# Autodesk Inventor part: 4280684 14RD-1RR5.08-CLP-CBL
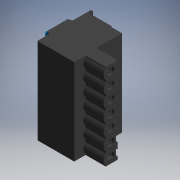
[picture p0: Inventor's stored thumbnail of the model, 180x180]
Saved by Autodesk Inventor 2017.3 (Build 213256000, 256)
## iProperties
Part Number: 4280684 14RD-1RR5.08-CLP-CBL
Material: Generic
Catalog Web Link: www.cadenas.de
Description: NEKM-C6 (p)-Terminal strip
Vendor: FESTO
Document SubType Name: Modeling
Designer: partserver
Manufacturer: FESTO
Mass: 12.0121 g
Surface Area: 60.2183 cm^2
Volume: 12.0121 cm^3
Density: 1 g/cm^3
Appearance: PSOLRGB-80-80-80
Category: PARTsolutions
Company: FESTO
Title: 4280684 14RD-1RR5.08-CLP-CBL
Author: Cadenas PARTsolutions
Comments: Terminal strip
PSOL_IDENT_0: {$CADENAS_DATA\23d-libs\festo\parts\n\nekm\parts\nekm_c6_parts.prj},201 {VTYP=3D},{NB=4280684 14RD-1
PSOL_IDENT_1: RR5.08-CLP-CBL},{LINA=4280684 14RD-1RR5.08-CLP-CBL},{NN=NEKM-C6 (p)},{DATE=16.05.2019 05:36:58},{GEO
PSOL_IDENT_2: MDATE=16.05.2019 05:36:56},{VERSION=},{LINEID=70},{WBVAR=},{WBNUMERIC=}  {NB=4280684 14RD-1RR5.08-CL
PSOL_IDENT_3: P-CBL},{LINA=4280684 14RD-1RR5.08-CLP-CBL},{KT=DUMMY},{TNR=4280684},{TYP=14RD-1RR5.08-CLP-CBL},{VERS=
PSOL_IDENT_4: 4},{N=7},{L=35.460},{L1=0.000}
NB: 4280684 14RD-1RR5.08-CLP-CBL
NN: NEKM-C6 (p)
NT: Terminal strip
NBSYN: $TNR. $TYP.
LINA: 4280684 14RD-1RR5.08-CLP-CBL
CATALOG: Festo
TNR: 4280684
TYP: 14RD-1RR5.08-CLP-CBL
VERS: 4
N: 7
L: 35.46
L1: 0
SUPPLIER: FESTO
ARTICLENO: 4280684 14RD-1RR5.08-CLP-CBL
BOMINFO: 4280684 14RD-1RR5.08-CLP-CBL
CREATOR: CADENAS GmbH
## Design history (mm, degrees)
sketch "Sketch_1"
  geometry: L1 (-0.5, -11.05)-(14.5, -11.05); L2 (14.7, -10.85)-(14.7, -6.415); L3 (14.897, -6.133)-(16.003, -5.731); L4 (16.2, -5.449)-(16.2, 2.789); L5 (16.003, 3.071)-(14.897, 3.473); L6 (14.7, 3.755)-(14.7, 10.85); L7 (14.5, 11.05)-(13.9, 11.05); L8 (13.9, 11.05)-(13.9, 9.15); L9 (13.9, 9.15)-(0, 9.15); L10 (0, 9.15)-(0, -0.584); L11 (0, -0.584)-(-0.5, -1.45); L12 (-0.5, -1.45)-(-0.5, -11.05); A1 r 0.2 centre (14.5, -10.85) between (14.5, -11.05) and (14.7, -10.85); A2 r 0.3 centre (15, -6.415) between (14.897, -6.133) and (14.7, -6.415); A3 r 0.3 centre (15.9, -5.449) between (16.003, -5.731) and (16.2, -5.449); A4 r 0.3 centre (15.9, 2.789) between (16.2, 2.789) and (16.003, 3.071); A5 r 0.3 centre (15, 3.755) between (14.7, 3.755) and (14.897, 3.473); A6 r 0.2 centre (14.5, 10.85) between (14.7, 10.85) and (14.5, 11.05)
  constraints: 24 end point, 12 point on circle, 6 centre point
extrude "Extrusion1" join sketch "Sketch_1" stored distance "d0" = 35.46; taper "d1" = 0 deg
sketch "Sketch_2"
  geometry: L1 (-17.29, 3.755)-(-17.29, 1.095); L2 (-17.29, 1.095)-(-13.19, 1.095); L3 (-13.19, 1.095)-(-13.19, 3.755); L4 (-13.19, 3.755)-(-17.29, 3.755)
  constraints: 8 end point
extrude "Extrusion2" cut sketch "Sketch_2" distance "d2" = 1.5; taper "d3" = 0 deg
pattern_linear "Rectangular Pattern1" dims "d6" = 5.08, "d9" = 7.51
sketch "Sketch_4"
  geometry: L1 (14.7, 1.095)-(16.7, 1.095); L2 (16.9, 1.295)-(16.9, 1.41); L3 (16.704, 1.654)-(16.036, 1.802); L4 (16.036, 2.388)-(16.704, 2.536); L5 (16.9, 2.78)-(16.9, 2.895); L6 (16.7, 3.095)-(14.7, 3.095); L7 (14.7, 3.095)-(14.7, 1.095); A1 r 0.2 centre (16.7, 1.295) between (16.7, 1.095) and (16.9, 1.295); A2 r 0.25 centre (16.65, 1.41) between (16.9, 1.41) and (16.704, 1.654); A3 r 0.3 centre (16.101, 2.095) between (16.036, 2.388) and (16.036, 1.802); A4 r 0.25 centre (16.65, 2.78) between (16.704, 2.536) and (16.9, 2.78); A5 r 0.2 centre (16.7, 2.895) between (16.9, 2.895) and (16.7, 3.095)
  constraints: 14 end point, 10 point on circle, 5 centre point
extrude "Extrusion3" join sketch "Sketch_4" distance "d10" = 3.9; taper "d11" = 0 deg
pattern_linear "Rectangular Pattern2" dims "d14" = 5.08, "d17" = 6.85
sketch "Sketch_6"
  geometry: L1 (-16.346, 3.695)-(-14.534, 3.695); L2 (-14.534, 7.595)-(-16.346, 7.595); L3 (-17.34, 6.651)-(-17.34, 4.639); A1 r 2.15 centre (-15.44, 5.645) between (-17.34, 4.639) and (-16.346, 3.695); A2 r 2.15 centre (-15.44, 5.645) between (-14.534, 3.695) and (-14.534, 7.595); A3 r 2.15 centre (-15.44, 5.645) between (-16.346, 7.595) and (-17.34, 6.651)
  constraints: 6 end point, 6 point on circle, 3 centre point
extrude "Extrusion4" cut sketch "Sketch_6" distance "d18" = 3.85; taper "d19" = 0 deg
pattern_linear "Rectangular Pattern3" dims "d22" = 13.95, "d25" = 0
sketch "Sketch_8"
  geometry: L1 (-11.266, 3.695)-(-9.454, 3.695); L2 (-9.454, 7.595)-(-11.266, 7.595); A1 r 2.15 centre (-10.36, 5.645) between (-11.266, 7.595) and (-11.266, 3.695); A2 r 2.15 centre (-10.36, 5.645) between (-9.454, 3.695) and (-9.454, 7.595)
  constraints: 4 end point, 4 point on circle, 2 centre point
extrude "Extrusion5" cut sketch "Sketch_8" distance "d26" = 3.85; taper "d27" = 0 deg
pattern_linear "Rectangular Pattern4" dims "d30" = 5.08, "d33" = 13.95
sketch "Sketch_10"
  geometry: L1 (-17.405, 9.15)-(-12.875, 9.15); A1 r 2.3 centre (-15.14, 8.75) between (-12.875, 9.15) and (-17.405, 9.15)
  constraints: 2 end point, 2 point on circle, 1 centre point
extrude "Extrusion6" join sketch "Sketch_10" distance "d34" = 9.7; taper "d35" = 0 deg
sketch "Pattern_5_SKETCH_1"
  geometry: L1 (-12.425, 9.15)-(-7.895, 9.15); A1 r 2.3 centre (-10.16, 8.75) between (-7.895, 9.15) and (-12.425, 9.15)
  constraints: 2 end point, 2 point on circle, 1 centre point
sketch "Pattern_5_SKETCH_2"
  geometry: L1 (-7.345, 9.15)-(-2.815, 9.15); A1 r 2.3 centre (-5.08, 8.75) between (-2.815, 9.15) and (-7.345, 9.15)
  constraints: 2 end point, 2 point on circle, 1 centre point
sketch "Pattern_5_SKETCH_3"
  geometry: L1 (-2.265, 9.15)-(2.265, 9.15); A1 r 2.3 centre (0, 8.75) between (2.265, 9.15) and (-2.265, 9.15)
  constraints: 2 end point, 2 point on circle, 1 centre point
sketch "Pattern_5_SKETCH_4"
  geometry: L1 (2.815, 9.15)-(7.345, 9.15); A1 r 2.3 centre (5.08, 8.75) between (7.345, 9.15) and (2.815, 9.15)
  constraints: 2 end point, 2 point on circle, 1 centre point
sketch "Pattern_5_SKETCH_5"
  geometry: L1 (7.895, 9.15)-(12.425, 9.15); A1 r 2.3 centre (10.16, 8.75) between (12.425, 9.15) and (7.895, 9.15)
  constraints: 2 end point, 2 point on circle, 1 centre point
sketch "Pattern_5_SKETCH_6"
  geometry: L1 (12.975, 9.15)-(17.505, 9.15); A1 r 2.3 centre (15.24, 8.75) between (17.505, 9.15) and (12.975, 9.15)
  constraints: 2 end point, 2 point on circle, 1 centre point
extrude "Extrusion7" join sketch "Pattern_5_SKETCH_1" distance "d36" = 9.7; taper "d37" = 0 deg
extrude "Extrusion8" join sketch "Pattern_5_SKETCH_2" distance "d38" = 9.7; taper "d39" = 0 deg
extrude "Extrusion9" join sketch "Pattern_5_SKETCH_3" distance "d40" = 9.7; taper "d41" = 0 deg
extrude "Extrusion10" join sketch "Pattern_5_SKETCH_4" distance "d42" = 9.7; taper "d43" = 0 deg
extrude "Extrusion11" join sketch "Pattern_5_SKETCH_5" distance "d44" = 9.7; taper "d45" = 0 deg
extrude "Extrusion12" join sketch "Pattern_5_SKETCH_6" distance "d46" = 9.7; taper "d47" = 0 deg
sketch "Sketch_12"
  geometry: L1 (2, 11.05)-(2, 9.15); L2 (2, 9.15)-(4.2, 9.15); L3 (4.2, 9.15)-(6.1, 11.05); L4 (6.1, 11.05)-(2, 11.05)
  constraints: 8 end point
extrude "Extrusion13" cut sketch "Sketch_12" stored distance "d48" = 35.46; taper "d49" = 0 deg
sketch "Sketch_13"
  geometry: L1 (-16.39, 9.305)-(-16.39, 8.155); L2 (-16.39, 8.155)-(-14.09, 8.155); L3 (-14.09, 8.155)-(-14.09, 9.305); A1 r 1.15 centre (-15.24, 9.305) between (-14.09, 9.305) and (-16.39, 9.305)
  constraints: 6 end point, 2 point on circle, 1 centre point
extrude "Extrusion14" cut sketch "Sketch_13" distance "d50" = 9.35; taper "d51" = 0 deg
pattern_linear "Rectangular Pattern5" dims "d54" = 5.08, "d57" = 0
sketch "Sketch_15"
  geometry: L1 (5.35, -16.39)-(6.5, -16.39); L2 (6.5, -16.39)-(6.5, -14.09); L3 (6.5, -14.09)-(5.35, -14.09); A1 r 1.15 centre (5.35, -15.24) between (5.35, -14.09) and (5.35, -16.39)
  constraints: 6 end point, 2 point on circle, 1 centre point
extrude "Extrusion15" cut sketch "Sketch_15" distance "d58" = 2.895; taper "d59" = 0 deg
pattern_linear "Rectangular Pattern6" dims "d62" = 5.08, "d65" = 0
sketch "Sketch_17"
  geometry: L1 (-17.73, -6.35)-(-17.34, -6.35); L2 (-13.14, -6.35)-(-12.26, -6.35); L3 (-8.06, -6.35)-(-7.18, -6.35); L4 (-2.98, -6.35)-(-2.1, -6.35); L5 (2.1, -6.35)-(2.98, -6.35); L6 (7.18, -6.35)-(8.06, -6.35); L7 (12.26, -6.35)-(13.14, -6.35); L8 (17.34, -6.35)-(17.73, -6.35); L9 (17.73, -6.35)-(17.73, -1.45); L10 (17.73, -1.45)-(16.5, -1.45); L11 (16.5, -1.45)-(16.893, -2.13); L12 (16.893, -2.13)-(13.587, -2.13); L13 (13.587, -2.13)-(13.98, -1.45); L14 (13.98, -1.45)-(11.42, -1.45); L15 (11.42, -1.45)-(11.813, -2.13); L16 (11.813, -2.13)-(8.507, -2.13); L17 (8.507, -2.13)-(8.9, -1.45); L18 (8.9, -1.45)-(6.34, -1.45); L19 (6.34, -1.45)-(6.733, -2.13); L20 (6.733, -2.13)-(3.427, -2.13); L21 (3.427, -2.13)-(3.82, -1.45); L22 (3.82, -1.45)-(1.26, -1.45); L23 (1.26, -1.45)-(1.653, -2.13); L24 (1.653, -2.13)-(-1.653, -2.13); L25 (-1.653, -2.13)-(-1.26, -1.45); L26 (-1.26, -1.45)-(-3.82, -1.45); L27 (-3.82, -1.45)-(-3.427, -2.13); L28 (-3.427, -2.13)-(-6.733, -2.13); L29 (-6.733, -2.13)-(-6.34, -1.45); L30 (-6.34, -1.45)-(-8.9, -1.45); L31 (-8.9, -1.45)-(-8.507, -2.13); L32 (-8.507, -2.13)-(-11.813, -2.13); L33 (-11.813, -2.13)-(-11.42, -1.45); L34 (-11.42, -1.45)-(-13.98, -1.45); L35 (-13.98, -1.45)-(-13.587, -2.13); L36 (-13.587, -2.13)-(-16.893, -2.13); L37 (-16.893, -2.13)-(-16.5, -1.45); L38 (-16.5, -1.45)-(-17.73, -1.45); L39 (-17.73, -1.45)-(-17.73, -6.35); A1 r 2.9 centre (-15.24, -4.35) between (-17.34, -6.35) and (-13.14, -6.35); A2 r 2.9 centre (-10.16, -4.35) between (-12.26, -6.35) and (-8.06, -6.35); A3 r 2.9 centre (-5.08, -4.35) between (-7.18, -6.35) and (-2.98, -6.35); A4 r 2.9 centre (0, -4.35) between (-2.1, -6.35) and (2.1, -6.35); A5 r 2.9 centre (5.08, -4.35) between (2.98, -6.35) and (7.18, -6.35); A6 r 2.9 centre (10.16, -4.35) between (8.06, -6.35) and (12.26, -6.35); A7 r 2.9 centre (15.24, -4.35) between (13.14, -6.35) and (17.34, -6.35)
  constraints: 78 end point, 14 point on circle, 7 centre point
extrude "Extrusion16" join sketch "Sketch_17" distance "d66" = 8.3; taper "d67" = 0 deg
sketch "Sketch17"
  geometry: 1 further point
hole "Hole1" sketch "Sketch17" at (15.24, -4.35) diameter "d68" = 1.4; stored, may be unused: countersink angle "d72" = 90 deg, drill point angle "d74" = 0 deg; dims "d69" = 6, "d70" = 3, "d71" = 1, "d73" = 2
pattern_linear "Rectangular Pattern7" dims "d77" = 5.08, "d80" = 0
sketch "Sketch_20"
  geometry: L1 (-8.8, -16.94)-(-7.8, -16.94); L2 (-7.8, -16.94)-(-7.8, -15.94); L3 (-7.8, -15.94)-(-8.8, -15.94); L4 (-8.8, -15.94)-(-8.8, -16.94)
  constraints: 8 end point
extrude "Extrusion17" join sketch "Sketch_20" stored distance "d81" = 4; taper "d82" = 0 deg
sketch "Sketch_21"
  geometry: L1 (-4.86, 0.292)-(-4.164, -0.11); L2 (-3.802, -0.062)-(-3.53, 0.21); L3 (-3.53, 0.21)-(-0.326, 0.35); L4 (-0.5, -0.449)-(-0.5, -2.76); L5 (-0.5, -2.76)-(0.5, -2.76); L6 (0.5, -2.76)-(0.5, 2.698); L7 (0.5, 2.698)-(0, 2.698); L8 (-0.233, 2.406)-(-3.754, 1.593); L9 (-4.115, 1.393)-(-4.901, 0.607); A1 r 0.2 centre (-4.76, 0.465) between (-4.901, 0.607) and (-4.86, 0.292); A2 r 0.3 centre (-4.014, 0.15) between (-4.164, -0.11) and (-3.802, -0.062); A3 r 0.3 centre (-0.3, 0.051) between (-0.3, -0.249) and (-0.326, 0.35); A4 r 0.2 centre (-0.3, -0.449) between (-0.3, -0.249) and (-0.5, -0.449); A5 r 0.3 centre (-0.3, 2.698) between (-0.233, 2.406) and (0, 2.698); A6 r 0.75 centre (-3.585, 0.862) between (-3.754, 1.593) and (-4.115, 1.393)
  constraints: 18 end point, 12 point on circle, 6 centre point
extrude "Extrusion18" join sketch "Sketch_21" distance "d83" = 1.6; taper "d84" = 0 deg
sketch "Sketch_22"
  geometry: L1 (-4.86, 0.292)-(-4.164, -0.11); L2 (-3.802, -0.062)-(-3.53, 0.21); L3 (-3.53, 0.21)-(-0.326, 0.35); L4 (-0.5, -0.449)-(-0.5, -2.76); L5 (-0.5, -2.76)-(0.5, -2.76); L6 (0.5, -2.76)-(0.5, 2.698); L7 (0.5, 2.698)-(0, 2.698); L8 (-0.233, 2.406)-(-3.754, 1.593); L9 (-4.115, 1.393)-(-4.901, 0.607); A1 r 0.2 centre (-4.76, 0.465) between (-4.901, 0.607) and (-4.86, 0.292); A2 r 0.3 centre (-4.014, 0.15) between (-4.164, -0.11) and (-3.802, -0.062); A3 r 0.3 centre (-0.3, 0.051) between (-0.3, -0.249) and (-0.326, 0.35); A4 r 0.2 centre (-0.3, -0.449) between (-0.3, -0.249) and (-0.5, -0.449); A5 r 0.3 centre (-0.3, 2.698) between (-0.233, 2.406) and (0, 2.698); A6 r 0.75 centre (-3.585, 0.862) between (-3.754, 1.593) and (-4.115, 1.393)
  constraints: 18 end point, 12 point on circle, 6 centre point
extrude "Extrusion19" join sketch "Sketch_22" distance "d85" = 1.6; taper "d86" = 0 deg
node "ANBAU_XY"
node "ANBAU_YZ"
node "ANBAU_ZX"
node "ANBAU_X"
node "ANBAU_Y"
node "ANBAU_Z"
node "ANBAU_Center"
body "Solid1"
